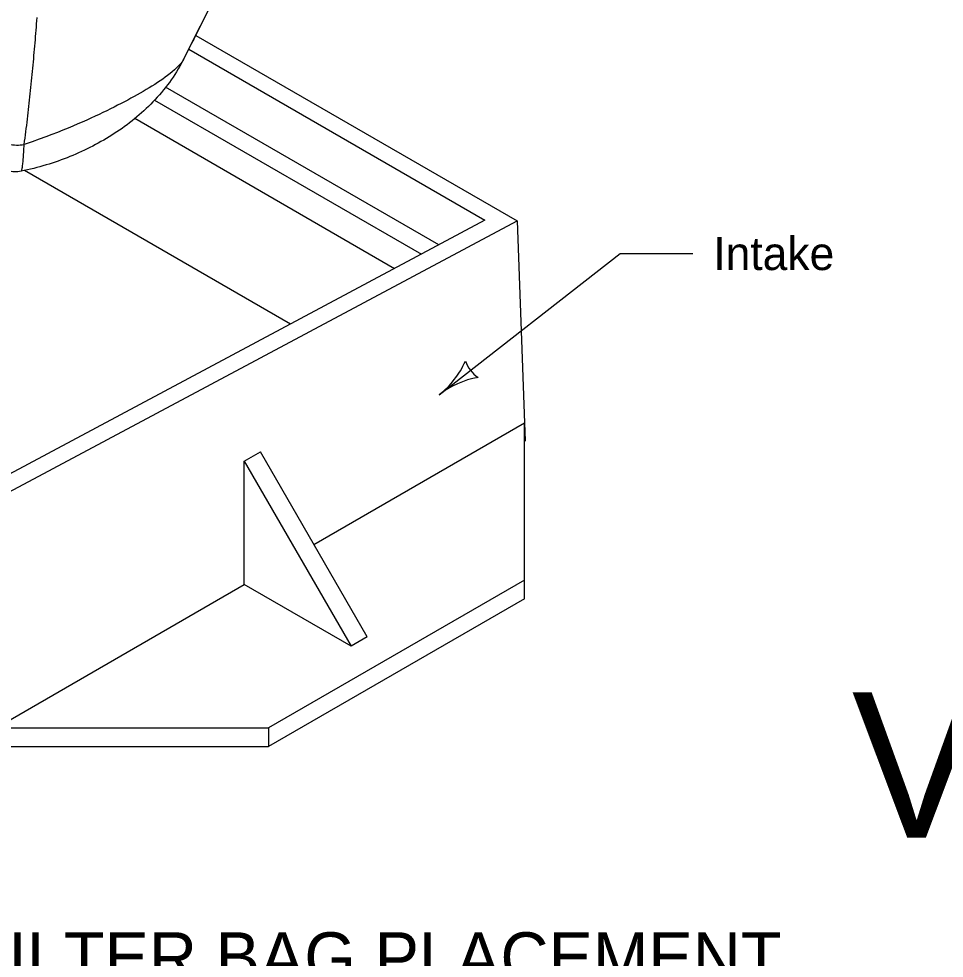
# Model space of a CAD drawing. Extents: x -4827 to -1483, y 910 to 4235.
# Drawn here: x -4144.1 to -3698, y 2119.8 to 2572.8 of the extents above; entities that cross this region are included whole.
import ezdxf

# ---------------------------------------------------------------- set-up
doc = ezdxf.new("R2010")
doc.units = 0
for name, color, linetype in [('Default', 7, 'Continuous'), ('dsnStdBlock', 7, 'Continuous'), ('dsnStdLabel', 7, 'Continuous'), ('dsnStdNote', 7, 'Continuous')]:
    doc.layers.add(name, color=color, linetype=linetype)

msp = doc.modelspace()

# ---------------------------------------------------------------- linework, layer by layer
at = {"layer": 'Default'}
for p, q in [((-4058.83, 2564.79), (-3903.9, 2475.36)), ((-4062.19, 2558.19), (-3919.45, 2475.65)), ((-3941.67, 2463.78), (-4073.39, 2539.95)), ((-4078.66, 2533.68), (-3950.04, 2459.31)), ((-4088.17, 2524.84), (-3962.94, 2452.42)), ((-4013.15, 2425.61), (-4141.31, 2499.67)), ((-4151.39, 2343.19), (-3903.9, 2475.36)), ((-3919.45, 2475.65), (-4151.31, 2351.82)), ((-3903.9, 2475.36), (-3900.35, 2377.98)), ((-4001.87, 2319.37), (-3900.35, 2377.98)), ((-3900.35, 2302.07), (-3900.35, 2377.98)), ((-3900.35, 2377.98), (-3900.03, 2369.23)), ((-3900.03, 2369.23), (-3900.35, 2369.05)), ((-4035.38, 2359.56), (-4027.65, 2364.02)), ((-3976.09, 2274.72), (-4027.65, 2364.02)), ((-4035.38, 2300.02), (-4035.38, 2359.56)), ((-4035.38, 2359.56), (-3983.82, 2270.25)), ((-3900.35, 2302.07), (-4023.78, 2230.81)), ((-3900.35, 2293.14), (-3900.35, 2302.07)), ((-4154.97, 2230.98), (-4035.38, 2300.02)), ((-3983.82, 2270.25), (-4035.38, 2300.02)), ((-3900.35, 2293.14), (-4023.78, 2221.88)), ((-3976.09, 2274.72), (-3983.82, 2270.25)), ((-4155.26, 2230.81), (-4023.78, 2230.81)), ((-4023.78, 2230.81), (-4023.78, 2221.88)), ((-4155.26, 2221.88), (-4023.78, 2221.88))]:
    msp.add_line(p, q, dxfattribs=at)
for points in [[(-3935.99, 2807.71), (-3952.2, 2775.96), (-3960.29, 2760.08), (-3968.38, 2744.19), (-3976.44, 2728.31), (-3984.5, 2712.41), (-3992.55, 2696.52), (-4000.58, 2680.62), (-4016.62, 2648.81), (-4024.63, 2632.9), (-4032.62, 2616.99), (-4048.61, 2585.15), (-4056.62, 2569.24), (-4064.67, 2553.33)], [(-4053.96, 2574.7), (-4054.93, 2572.74), (-4055.91, 2570.79), (-4056.88, 2568.84), (-4057.85, 2566.89), (-4058.83, 2564.94), (-4059.8, 2562.99), (-4060.78, 2561.05), (-4061.75, 2559.11), (-4062.73, 2557.16), (-4063.71, 2555.23), (-4064.69, 2553.29)], [(-4141.5, 2512.27), (-4141.29, 2513.79), (-4141.09, 2515.32), (-4140.88, 2516.84), (-4140.69, 2518.37), (-4140.49, 2519.9), (-4140.3, 2521.43), (-4140.12, 2522.96), (-4139.93, 2524.48), (-4139.75, 2526.01), (-4139.57, 2527.54), (-4139.4, 2529.07), (-4139.23, 2530.6), (-4139.06, 2532.13), (-4138.89, 2533.66), (-4138.73, 2535.2), (-4138.57, 2536.73), (-4138.41, 2538.26), (-4138.25, 2539.79), (-4138.1, 2541.32), (-4137.94, 2542.85), (-4137.79, 2544.38), (-4137.65, 2545.91), (-4137.5, 2547.44), (-4137.35, 2548.97), (-4137.21, 2550.5), (-4137.07, 2552.03), (-4136.93, 2553.56), (-4136.79, 2555.08), (-4136.66, 2556.61), (-4136.52, 2558.14), (-4136.39, 2559.67), (-4136.26, 2561.2), (-4136.13, 2562.72), (-4136, 2564.25), (-4135.87, 2565.78), (-4135.74, 2567.3), (-4135.62, 2568.83), (-4135.5, 2570.35), (-4135.37, 2571.88), (-4135.25, 2573.4)], [(-4064.97, 2552.75), (-4065.7, 2551.37), (-4066.46, 2550.01), (-4067.24, 2548.67), (-4068.05, 2547.34), (-4068.89, 2546.02), (-4069.74, 2544.73), (-4070.62, 2543.45), (-4071.52, 2542.19), (-4072.44, 2540.94), (-4073.38, 2539.72), (-4074.34, 2538.51), (-4075.32, 2537.33), (-4076.32, 2536.16), (-4077.33, 2535.01), (-4078.37, 2533.88), (-4079.41, 2532.77), (-4080.48, 2531.68), (-4081.56, 2530.61), (-4082.66, 2529.55), (-4083.77, 2528.51), (-4084.89, 2527.49), (-4086.03, 2526.49), (-4087.18, 2525.51), (-4088.35, 2524.55), (-4089.52, 2523.61), (-4090.71, 2522.68), (-4091.9, 2521.77), (-4093.11, 2520.88), (-4094.34, 2520), (-4095.57, 2519.15), (-4096.81, 2518.3), (-4098.07, 2517.48), (-4099.33, 2516.67), (-4100.6, 2515.88), (-4101.89, 2515.1), (-4103.18, 2514.34), (-4104.48, 2513.6), (-4105.8, 2512.87), (-4107.12, 2512.15), (-4108.45, 2511.46), (-4109.79, 2510.77), (-4111.14, 2510.1), (-4112.5, 2509.45), (-4113.87, 2508.81), (-4115.25, 2508.19), (-4116.63, 2507.58), (-4118.03, 2506.98), (-4119.43, 2506.41), (-4120.85, 2505.84), (-4122.27, 2505.3), (-4123.7, 2504.76), (-4125.14, 2504.25), (-4126.58, 2503.75), (-4128.03, 2503.26), (-4129.5, 2502.79), (-4130.97, 2502.34), (-4132.45, 2501.9), (-4133.94, 2501.48), (-4135.43, 2501.08), (-4136.93, 2500.69), (-4138.44, 2500.32), (-4139.96, 2499.97), (-4141.48, 2499.64), (-4143.01, 2499.33)], [(-4064.68, 2553.28), (-4065.36, 2552.16), (-4066.18, 2551.1), (-4067.07, 2550.1), (-4068.03, 2549.14), (-4069.04, 2548.2), (-4070.1, 2547.29), (-4071.21, 2546.39), (-4072.35, 2545.5), (-4073.53, 2544.63), (-4074.74, 2543.76), (-4075.98, 2542.91), (-4077.26, 2542.06), (-4078.57, 2541.21), (-4079.9, 2540.37), (-4081.27, 2539.53), (-4082.66, 2538.69), (-4084.08, 2537.86), (-4085.52, 2537.02), (-4086.99, 2536.19), (-4088.49, 2535.35), (-4090.02, 2534.51), (-4091.57, 2533.68), (-4093.16, 2532.84), (-4094.79, 2531.99), (-4096.45, 2531.14), (-4098.15, 2530.28), (-4099.9, 2529.41), (-4101.69, 2528.53), (-4103.52, 2527.65), (-4105.41, 2526.75), (-4107.34, 2525.85), (-4109.33, 2524.94), (-4111.38, 2524.01), (-4113.5, 2523.07), (-4115.7, 2522.11), (-4117.99, 2521.13), (-4120.36, 2520.14), (-4122.84, 2519.12), (-4125.44, 2518.08), (-4128.2, 2517), (-4131.13, 2515.89), (-4134.26, 2514.74), (-4137.67, 2513.54), (-4141.48, 2512.27)], [(-4064.69, 2553.29), (-4064.7, 2553.27), (-4064.71, 2553.24), (-4064.72, 2553.22), (-4064.73, 2553.2), (-4064.74, 2553.18), (-4064.76, 2553.15), (-4064.77, 2553.13), (-4064.78, 2553.11), (-4064.79, 2553.09), (-4064.8, 2553.06), (-4064.81, 2553.04), (-4064.83, 2553.02), (-4064.84, 2552.99), (-4064.85, 2552.97), (-4064.86, 2552.95), (-4064.87, 2552.93), (-4064.88, 2552.9), (-4064.9, 2552.88), (-4064.91, 2552.86), (-4064.92, 2552.84), (-4064.93, 2552.81), (-4064.94, 2552.79), (-4064.95, 2552.77), (-4064.97, 2552.75)], [(-4143.01, 2499.33), (-4142.93, 2499.37), (-4142.86, 2499.45), (-4142.79, 2499.57), (-4142.72, 2499.74), (-4142.65, 2499.96), (-4142.58, 2500.22), (-4142.51, 2500.52), (-4142.45, 2500.86), (-4142.38, 2501.25), (-4142.32, 2501.69), (-4142.26, 2502.16), (-4142.2, 2502.68), (-4142.13, 2503.25), (-4142.07, 2503.86), (-4142.01, 2504.52), (-4141.95, 2505.21), (-4141.9, 2505.95), (-4141.84, 2506.74), (-4141.78, 2507.56), (-4141.72, 2508.43), (-4141.67, 2509.33), (-4141.61, 2510.27), (-4141.55, 2511.25), (-4141.5, 2512.27)], [(-4143.01, 2499.33), (-4143.79, 2499.2), (-4144.57, 2499.11), (-4145.36, 2499.06), (-4146.16, 2499.06), (-4146.95, 2499.1), (-4147.73, 2499.18), (-4148.51, 2499.3), (-4149.28, 2499.46)]]:
    msp.add_lwpolyline(points, dxfattribs=at)
for centre, major_axis, ratio, start_param, end_param in [((-4077.67, 2559.92), (13.01, -6.59), 0.511769, 6.277086, 6.283185), ((-4145.12, 2523.9), (14.57, -0.63), 0.819834, 4.478279, 4.998939)]:
    msp.add_ellipse(centre, major_axis=major_axis, ratio=ratio, start_param=start_param, end_param=end_param, dxfattribs=at)
at = {"layer": 'dsnStdBlock'}
msp.add_lwpolyline([(-3941.51, 2391.49), (-3854.24, 2459.66), (-3819.24, 2459.66)], dxfattribs=at)
at = {"layer": 'dsnStdLabel'}
for centre, radius, start, end in [((-3967.68, 2424.98), 42.5, 307.9935, 336.066), ((-3913.43, 2413.42), 16.42, 200.2601, 235.7268), ((-3915.35, 2357.99), 42.5, 99.921, 127.9935)]:
    msp.add_arc(centre, radius, start, end, dxfattribs=at)

# ---------------------------------------------------------------- texts
at = {"layer": 'Default'}
msp.add_text('TYPICAL SEDIMENT FILTER BAG PLACEMENT', height=24, dxfattribs=at).set_placement((-4486.17, 2108.26))
at = {"layer": 'dsnStdBlock'}
msp.add_text('VOIDED Now EC-604', height=70, dxfattribs=at).set_placement((-3742.53, 2177.94))
at = {"layer": 'dsnStdNote'}
msp.add_text('Intake', height=16, dxfattribs=at).set_placement((-3809.28, 2451.66))

doc.saveas('drawing.dxf')
